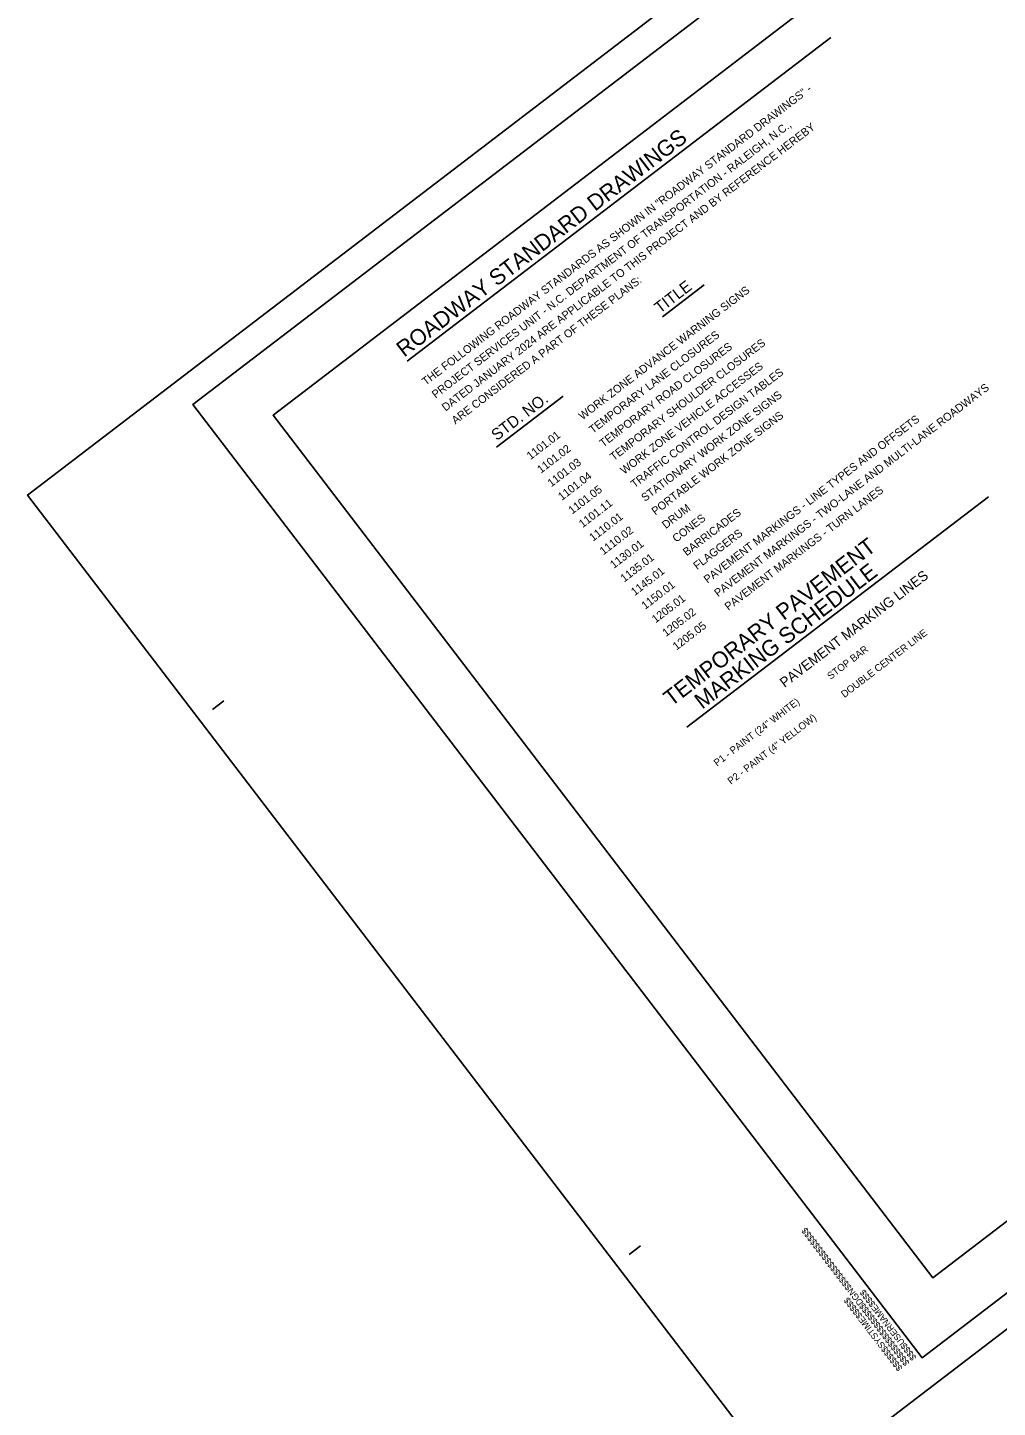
# Model space of a CAD drawing. Extents: x -642 to 2005, y -4412 to 1950.
# Drawn here: x -5 to 844, y 126 to 1333 of the extents above; entities that cross this region are included whole.
import ezdxf

# ---------------------------------------------------------------- set-up
doc = ezdxf.new("R2010")
doc.units = 0
for name, color, linetype in [('DEV BORDER CELL', 7, 'Continuous'), ('Scratch_Level_0', 7, 'Continuous'), ('Sheet Plot Border Outside CELL', 7, 'Continuous')]:
    doc.layers.add(name, color=color, linetype=linetype)

msp = doc.modelspace()

# ---------------------------------------------------------------- linework, layer by layer
at = {"layer": 'DEV BORDER CELL'}
for p, q in [((327.4, 1041.2), (698, 1324.6)), ((550.8, 1080.1), (587.4, 1108)), ((140.9, 1004), (140.9, 1004)), ((405.7, 966), (464, 1010.6)), ((572.2, 721), (835.9, 922.7)), ((157.3, 736.4), (167.2, 744)), ((521.8, 259.8), (531.7, 267.4)), ((777.9, 169.3), (777.9, 169.3))]:
    msp.add_line(p, q, dxfattribs=at)
msp.add_lwpolyline([(1331.7, 1914.5), (140.1, 1003.4), (777.9, 169.3), (1969.5, 1080.4)], close=True, dxfattribs=at)
at = {"layer": 'Scratch_Level_0'}
msp.add_lwpolyline([(1322.3, 1844.4), (210.2, 994), (787.3, 239.4), (1485.4, 773.2), (1413.6, 867.2), (1827.6, 1183.7)], close=True, dxfattribs=at)
at = {"layer": 'Sheet Plot Border Outside CELL'}
msp.add_lwpolyline([(663.6, 50.4), (2004.5, 1075.8), (1336.4, 1949.6), (-4.5, 924.2)], close=True, dxfattribs=at)

# ---------------------------------------------------------------- texts
at = {"layer": 'DEV BORDER CELL'}
for s, height, rotation, p in [('THE FOLLOWING ROADWAY STANDARDS AS SHOWN IN "ROADWAY STANDARD DRAWINGS" -', 7, 37.4042, (343.8, 1019.7)), ('ROADWAY STANDARD DRAWINGS', 13.999, 37.4042, (324.9, 1044.3)), ('PROJECT SERVICES UNIT - N.C. DEPARTMENT OF TRANSPORTATION - RALEIGH, N.C.,', 7, 37.4042, (352.4, 1008.4)), ('DATED JANUARY 2024 ARE APPLICABLE TO THIS PROJECT AND BY REFERENCE HEREBY', 7, 37.4042, (361.1, 997.1)), ('ARE CONSIDERED A PART OF THESE PLANS:', 7, 37.4042, (369.7, 985.8)), ('TITLE', 10, 37.4042, (548.6, 1082.7)), ('1101.01         WORK ZONE ADVANCE WARNING SIGNS', 7, 37.4444, (435.4, 954.7)), ('1101.02         TEMPORARY LANE CLOSURES', 7, 37.4444, (444.5, 942.8)), ('1101.03         TEMPORARY ROAD CLOSURES', 7, 37.4444, (453.6, 930.9)), ('1101.04         TEMPORARY SHOULDER CLOSURES', 7, 37.4444, (462.8, 919)), ('1101.05         WORK ZONE VEHICLE ACCESSES', 7, 37.4444, (471.9, 907.1)), ('1101.11         TRAFFIC CONTROL DESIGN TABLES', 7, 37.4444, (481, 895.2)), ('1110.01         STATIONARY WORK ZONE SIGNS', 7, 37.4444, (490.1, 883.3)), ('1205.02         PAVEMENT MARKINGS - TWO-LANE AND MULTI-LANE ROADWAYS', 7, 37.4444, (554, 799.9)), ('STD. NO.', 10, 37.4042, (405.9, 971.3)), ('1110.02         PORTABLE WORK ZONE SIGNS', 7, 37.4444, (499.2, 871.4)), ('1205.01         PAVEMENT MARKINGS - LINE TYPES AND OFFSETS', 7, 37.4444, (544.8, 811.8)), ('1205.05         PAVEMENT MARKINGS - TURN LANES', 7, 37.4444, (563.1, 788)), ('1130.01         DRUM ', 7, 37.4444, (508.3, 859.5)), ('1135.01         CONES', 7, 37.4444, (517.4, 847.6)), ('1145.01         BARRICADES', 7, 37.4444, (526.6, 835.7)), ('1150.01         FLAGGERS', 7, 37.4444, (535.7, 823.7)), ('TEMPORARY PAVEMENT', 13.999, 37.404, (558.6, 738.8)), ('MARKING SCHEDULE', 13.999, 37.404, (585.6, 736.3)), ('PAVEMENT MARKING LINES', 8.75, 37.404, (657.7, 755.3)), ('DOUBLE CENTER LINE', 6.25, 37.404, (710, 746.5)), ('STOP BAR', 6.25, 37.404, (697.9, 762.4)), ('P1 - PAINT (24" WHITE)', 6.25, 37.404, (598.6, 686.5)), ('P2 - PAINT (4" YELLOW)', 6.25, 37.404, (610.7, 670.6)), ('$$$$$$$$$$$$$$$$DGN$$$$$$$$$$$$$$$$', 5.584, 127.404, (767.2, 165)), ('$$$$$$SYSTIME$$$$$', 5.584, 127.404, (761.2, 160.4)), ('$$$$USERNAME$$$$', 5.584, 127.404, (773.3, 169.6))]:
    msp.add_text(s, height=height, rotation=rotation, dxfattribs=at).set_placement(p)

doc.saveas('drawing.dxf')
